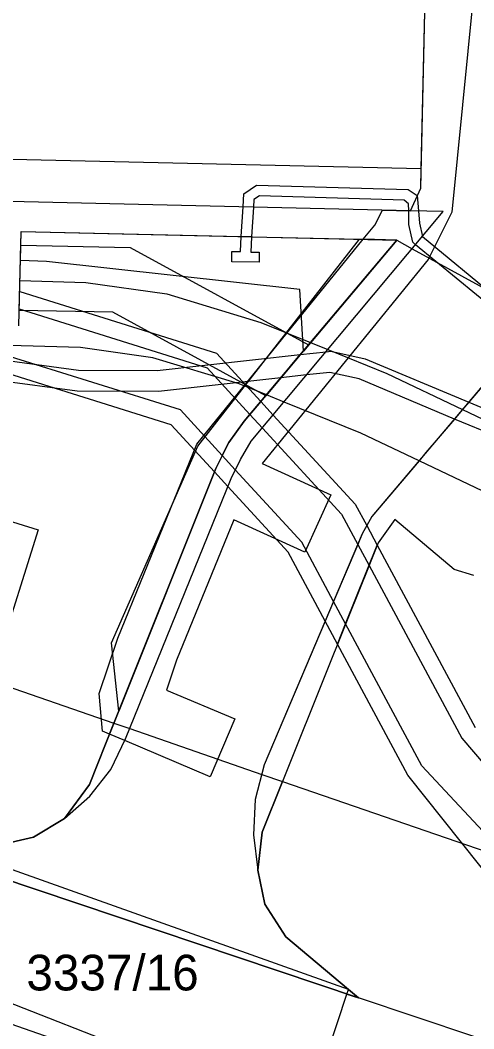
# Model space of a CAD drawing. Extents: x -593183 to -588034, y -1130415 to -1124994.
# Drawn here: x -592256.65 to -592235.02, y -1128440.03 to -1128391.95 of the extents above; entities that cross this region are included whole.
import ezdxf

# ---------------------------------------------------------------- set-up
doc = ezdxf.new("R2010")
doc.units = 0
for name, color, linetype in [('Vrstva 1', 7, 'Continuous'), ('Vrstva 18', 7, 'Continuous'), ('Vrstva 27', 7, 'Continuous')]:
    doc.layers.add(name, color=color, linetype=linetype)

msp = doc.modelspace()

# ---------------------------------------------------------------- linework, layer by layer
at = {"layer": 'Vrstva 1'}
for p, q in [((-592237.53, -1128399.02), (-592237.22, -1128385.45)), ((-592275.54, -1128398.15), (-592237.53, -1128399.02)), ((-592237.55, -1128399.95), (-592237.53, -1128399.02)), ((-592238.04, -1128401.03), (-592237.55, -1128399.95)), ((-592256.71, -1128406.52), (-592256.61, -1128402.02)), ((-592256.61, -1128402.02), (-592238.68, -1128402.43)), ((-592245.97, -1128411.07), (-592238.68, -1128402.43)), ((-592246.7, -1128412.08), (-592245.97, -1128411.07)), ((-592247.32, -1128413.32), (-592246.7, -1128412.08)), ((-592253.35, -1128428.39), (-592247.32, -1128413.32)), ((-592238.79, -1128415.75), (-592239.58, -1128416.86)), ((-592235.96, -1128418.14), (-592238.79, -1128415.75)), ((-592239.58, -1128416.86), (-592245.11, -1128430.66)), ((-592235.01, -1128418.42), (-592235.96, -1128418.14)), ((-592292.81, -1128424.89), (-592233.79, -1128447.89)), ((-592293.27, -1128427.22), (-592233.79, -1128447.89)), ((-592254.54, -1128430), (-592253.35, -1128428.39)), ((-592256.01, -1128430.9), (-592254.54, -1128430)), ((-592257.79, -1128431.31), (-592256.01, -1128430.9)), ((-592245.11, -1128430.66), (-592245.32, -1128432.47)), ((-592262.05, -1128431.32), (-592240.51, -1128438.56)), ((-592245.32, -1128432.47), (-592244.98, -1128434.09)), ((-592244.98, -1128434.09), (-592243.98, -1128435.65)), ((-592243.98, -1128435.65), (-592240.51, -1128438.56)), ((-592235.02, -1128440.4), (-592240.51, -1128438.56))]:
    msp.add_line(p, q, dxfattribs=at)
for points in [[(-592211.75, -1128388.7), (-592213.01, -1128392.48), (-592216.38, -1128400.85), (-592217.2, -1128402.32), (-592218.27, -1128403.62), (-592219.56, -1128404.7), (-592221.41, -1128405.52), (-592223.4, -1128405.89), (-592230.17, -1128405.79), (-592231.22, -1128405.97), (-592232.15, -1128406.49), (-592239.88, -1128415.6), (-592240.34, -1128416.44), (-592245.01, -1128427.45), (-592245.44, -1128429.09), (-592245.52, -1128430.78), (-592245.32, -1128432.47)], [(-592238.04, -1128401.03), (-592277.64, -1128400.11), (-592277.61, -1128398.63), (-592281.59, -1128398.55), (-592281.41, -1128392.14), (-592283.39, -1128392.47), (-592285.17, -1128393.38), (-592286.61, -1128394.54), (-592287.74, -1128396), (-592288.65, -1128397.62)], [(-592254.54, -1128430), (-592253.32, -1128428.94), (-592252.33, -1128427.66), (-592251.62, -1128426.21), (-592246.59, -1128413.8), (-592246.14, -1128412.89), (-592245.63, -1128412.02), (-592236.47, -1128401.07), (-592238.04, -1128401.03)]]:
    msp.add_lwpolyline(points, dxfattribs=at)
at = {"layer": 'Vrstva 27'}
for p, q in [((-592237.55, -1128399.95), (-592237.22, -1128385.45)), ((-592235.02, -1128390.64), (-592236.07, -1128401.1)), ((-592245.98, -1128400.22), (-592245.38, -1128399.82)), ((-592245.38, -1128399.82), (-592238.14, -1128400.02)), ((-592238.14, -1128400.02), (-592237.71, -1128400.3)), ((-592238.04, -1128401.03), (-592237.55, -1128399.95)), ((-592246.02, -1128400.84), (-592245.98, -1128400.22)), ((-592245.5, -1128400.5), (-592245.52, -1128400.86)), ((-592245.24, -1128400.32), (-592245.5, -1128400.5)), ((-592238.34, -1128400.52), (-592245.24, -1128400.32)), ((-592238.13, -1128400.7), (-592238.34, -1128400.52)), ((-592237.71, -1128400.3), (-592237.65, -1128401.04)), ((-592246.11, -1128402.26), (-592246.02, -1128400.84)), ((-592245.52, -1128400.86), (-592245.61, -1128402.27)), ((-592239.74, -1128401.72), (-592239.37, -1128401)), ((-592239.37, -1128401), (-592238.04, -1128401.03)), ((-592238.12, -1128401.03), (-592238.13, -1128400.7)), ((-592238.12, -1128401.2), (-592238.12, -1128401.03)), ((-592237.65, -1128401.04), (-592237.61, -1128401.63)), ((-592236.07, -1128401.1), (-592237.2, -1128403.35)), ((-592238.11, -1128401.69), (-592238.12, -1128401.2)), ((-592237.61, -1128401.63), (-592237.46, -1128402.26)), ((-592256.64, -1128403.4), (-592256.61, -1128402.02)), ((-592256.62, -1128402.68), (-592256.61, -1128402.02)), ((-592256.61, -1128402.02), (-592238.68, -1128402.43)), ((-592256.61, -1128402.02), (-592246.11, -1128402.26)), ((-592240.29, -1128402.39), (-592239.74, -1128401.72)), ((-592237.93, -1128402.53), (-592238.11, -1128401.69)), ((-592248.22, -1128412.16), (-592240.29, -1128402.39)), ((-592248.18, -1128412.26), (-592240.46, -1128402.39)), ((-592246.15, -1128402.98), (-592246.11, -1128402.26)), ((-592245.61, -1128402.27), (-592246.11, -1128402.26)), ((-592246.11, -1128402.26), (-592245.61, -1128402.27)), ((-592246.11, -1128402.26), (-592245.61, -1128402.27)), ((-592238.68, -1128402.43), (-592245.97, -1128411.07)), ((-592245.97, -1128411.07), (-592238.68, -1128402.43)), ((-592238.68, -1128402.43), (-592245.97, -1128411.07)), ((-592245.97, -1128411.07), (-592238.68, -1128402.43)), ((-592245.61, -1128402.27), (-592245.65, -1128403)), ((-592245.61, -1128402.27), (-592240.46, -1128402.39)), ((-592238.68, -1128402.43), (-592243.14, -1128407.72)), ((-592238.68, -1128402.43), (-592242.8, -1128407.32)), ((-592240.46, -1128402.39), (-592238.68, -1128402.43)), ((-592240.46, -1128402.39), (-592240.29, -1128402.39)), ((-592240.29, -1128402.39), (-592238.68, -1128402.43)), ((-592240.29, -1128402.39), (-592238.68, -1128402.43)), ((-592238.68, -1128402.43), (-592240.29, -1128402.39)), ((-592238.68, -1128402.43), (-592237.95, -1128402.84)), ((-592237.79, -1128402.65), (-592237.93, -1128402.53)), ((-592237.46, -1128402.26), (-592232.23, -1128406.59)), ((-592256.69, -1128405.78), (-592256.62, -1128402.68)), ((-592256.64, -1128403.18), (-592256.62, -1128402.68)), ((-592256.62, -1128402.68), (-592251.41, -1128402.78)), ((-592251.41, -1128402.78), (-592242.9, -1128407.43)), ((-592246.56, -1128403.47), (-592246.55, -1128402.98)), ((-592246.55, -1128402.98), (-592246.15, -1128402.98)), ((-592245.65, -1128403), (-592245.25, -1128403)), ((-592245.25, -1128403), (-592245.26, -1128403.49)), ((-592237.95, -1128402.84), (-592231.74, -1128406.26)), ((-592232.56, -1128406.97), (-592237.79, -1128402.65)), ((-592256.64, -1128403.4), (-592256.64, -1128403.18)), ((-592255.4, -1128403.45), (-592256.64, -1128403.4)), ((-592255.4, -1128403.45), (-592256.64, -1128403.4)), ((-592243.32, -1128404.79), (-592255.4, -1128403.45)), ((-592243.32, -1128404.79), (-592255.4, -1128403.45)), ((-592245.26, -1128403.49), (-592246.56, -1128403.47)), ((-592237.2, -1128403.35), (-592245.11, -1128413.08)), ((-592256.66, -1128404.36), (-592253.52, -1128404.45)), ((-592253.52, -1128404.45), (-592249.65, -1128405)), ((-592256.67, -1128404.88), (-592247.29, -1128407.82)), ((-592249.65, -1128405), (-592245.17, -1128406.36)), ((-592243.14, -1128407.72), (-592243.32, -1128404.79)), ((-592243.14, -1128407.72), (-592243.32, -1128404.79)), ((-592256.69, -1128405.7), (-592247.73, -1128408.52)), ((-592256.69, -1128405.7), (-592247.73, -1128408.52)), ((-592252.23, -1128405.86), (-592256.69, -1128405.78)), ((-592244.94, -1128409.85), (-592252.23, -1128405.86)), ((-592245.17, -1128406.36), (-592242.8, -1128407.32)), ((-592253.78, -1128407.55), (-592265.26, -1128407.21)), ((-592242.8, -1128407.32), (-592244.91, -1128409.81)), ((-592244.91, -1128409.81), (-592242.8, -1128407.32)), ((-592242.8, -1128407.32), (-592242.9, -1128407.43)), ((-592242.8, -1128407.32), (-592241.98, -1128407.65)), ((-592232.56, -1128406.97), (-592235.26, -1128410.15)), ((-592261.52, -1128407.61), (-592253.87, -1128408.63)), ((-592250.32, -1128408.04), (-592253.78, -1128407.55)), ((-592250.12, -1128408.65), (-592243.29, -1128407.89)), ((-592247.29, -1128407.82), (-592245.17, -1128410.12)), ((-592242.9, -1128407.43), (-592244.94, -1128409.85)), ((-592243.29, -1128407.89), (-592244.22, -1128409)), ((-592244.22, -1128409), (-592243.29, -1128407.89)), ((-592243.29, -1128407.89), (-592242.06, -1128407.76)), ((-592242.9, -1128407.43), (-592243.14, -1128407.72)), ((-592242.06, -1128407.76), (-592241.83, -1128407.73)), ((-592241.98, -1128407.65), (-592239.16, -1128408.79)), ((-592241.83, -1128407.73), (-592240.19, -1128408.09)), ((-592249.01, -1128410.53), (-592257.36, -1128407.91)), ((-592246.21, -1128409.28), (-592250.32, -1128408.04)), ((-592240.19, -1128408.09), (-592235.26, -1128410.15)), ((-592253.93, -1128409.63), (-592261.6, -1128408.61)), ((-592249.45, -1128411.23), (-592257.49, -1128408.71)), ((-592249.45, -1128411.23), (-592257.49, -1128408.71)), ((-592253.87, -1128408.63), (-592250.12, -1128408.65)), ((-592247.73, -1128408.52), (-592245.69, -1128410.74)), ((-592247.73, -1128408.52), (-592245.69, -1128410.74)), ((-592242.99, -1128408.86), (-592244.22, -1128409)), ((-592241.89, -1128408.74), (-592242.99, -1128408.86)), ((-592240.49, -1128409.05), (-592241.89, -1128408.74)), ((-592239.16, -1128408.79), (-592235.56, -1128410.51)), ((-592244.22, -1128409), (-592250.06, -1128409.65)), ((-592244.91, -1128409.81), (-592246.21, -1128409.28)), ((-592235.94, -1128410.96), (-592240.49, -1128409.05)), ((-592250.06, -1128409.65), (-592253.93, -1128409.63)), ((-592244.06, -1128410.15), (-592244.91, -1128409.81)), ((-592245.17, -1128410.12), (-592245.97, -1128411.07)), ((-592245.97, -1128411.07), (-592245.17, -1128410.12)), ((-592245.17, -1128410.12), (-592244.58, -1128410.77)), ((-592240.4, -1128411.63), (-592244.06, -1128410.15)), ((-592235.26, -1128410.15), (-592235.56, -1128410.51)), ((-592235.26, -1128410.15), (-592232.71, -1128411.22)), ((-592247.01, -1128412.7), (-592249.01, -1128410.53)), ((-592245.69, -1128410.74), (-592245.97, -1128411.07)), ((-592245.69, -1128410.74), (-592245.97, -1128411.07)), ((-592245.97, -1128411.07), (-592245.69, -1128410.74)), ((-592245.69, -1128410.74), (-592245.1, -1128411.39)), ((-592244.58, -1128410.77), (-592240.67, -1128415.02)), ((-592235.56, -1128410.51), (-592235.89, -1128410.9)), ((-592235.56, -1128410.51), (-592230.04, -1128413.13)), ((-592247.38, -1128413.48), (-592249.45, -1128411.23)), ((-592247.38, -1128413.48), (-592249.45, -1128411.23)), ((-592245.97, -1128411.07), (-592246.7, -1128412.08)), ((-592246.7, -1128412.08), (-592245.97, -1128411.07)), ((-592245.97, -1128411.07), (-592246.7, -1128412.08)), ((-592245.97, -1128411.07), (-592246.7, -1128412.08)), ((-592245.97, -1128411.07), (-592246.7, -1128412.08)), ((-592245.97, -1128411.07), (-592246.7, -1128412.08)), ((-592246.7, -1128412.08), (-592245.97, -1128411.07)), ((-592246.7, -1128412.08), (-592245.97, -1128411.07)), ((-592246.7, -1128412.08), (-592245.97, -1128411.07)), ((-592235.94, -1128410.96), (-592237.3, -1128412.55)), ((-592235.89, -1128410.9), (-592235.94, -1128410.96)), ((-592233.11, -1128412.14), (-592235.94, -1128410.96)), ((-592245.1, -1128411.39), (-592241.33, -1128415.49)), ((-592237.63, -1128412.95), (-592240.4, -1128411.63)), ((-592252, -1128421.4), (-592248.22, -1128412.16)), ((-592246.7, -1128412.08), (-592247.32, -1128413.32)), ((-592247.32, -1128413.32), (-592246.7, -1128412.08)), ((-592246.7, -1128412.08), (-592247.32, -1128413.32)), ((-592247.32, -1128413.32), (-592246.7, -1128412.08)), ((-592247.32, -1128413.32), (-592246.7, -1128412.08)), ((-592246.7, -1128412.08), (-592247.01, -1128412.7)), ((-592246.7, -1128412.08), (-592247.01, -1128412.7)), ((-592246.7, -1128412.08), (-592247.01, -1128412.7)), ((-592247.01, -1128412.7), (-592246.7, -1128412.08)), ((-592252.3, -1128421.63), (-592248.18, -1128412.26)), ((-592247.01, -1128412.7), (-592247.32, -1128413.32)), ((-592247.01, -1128412.7), (-592247.32, -1128413.32)), ((-592246.39, -1128413.39), (-592247.01, -1128412.7)), ((-592237.3, -1128412.55), (-592237.63, -1128412.95)), ((-592265.44, -1128413.19), (-592255.79, -1128416.25)), ((-592245.11, -1128413.08), (-592241.84, -1128414.57)), ((-592237.63, -1128412.95), (-592239.88, -1128415.6)), ((-592232.11, -1128415.58), (-592237.63, -1128412.95)), ((-592253.35, -1128428.39), (-592247.32, -1128413.32)), ((-592247.32, -1128413.32), (-592252.39, -1128425.99)), ((-592252.39, -1128425.99), (-592247.32, -1128413.32)), ((-592247.32, -1128413.32), (-592251.95, -1128424.89)), ((-592247.32, -1128413.32), (-592247.38, -1128413.48)), ((-592247.32, -1128413.32), (-592247.38, -1128413.48)), ((-592247.38, -1128413.48), (-592247.32, -1128413.32)), ((-592246.74, -1128414.18), (-592247.38, -1128413.48)), ((-592243.22, -1128416.83), (-592246.39, -1128413.39)), ((-592243.87, -1128417.3), (-592246.74, -1128414.18)), ((-592241.84, -1128414.57), (-592243.08, -1128417.3)), ((-592240.67, -1128415.02), (-592240.12, -1128416.04)), ((-592241.33, -1128415.49), (-592240.55, -1128416.94)), ((-592239.88, -1128415.6), (-592240.12, -1128416.04)), ((-592246.46, -1128415.76), (-592249.19, -1128422.45)), ((-592243.08, -1128417.3), (-592246.46, -1128415.76)), ((-592240.12, -1128416.04), (-592240.34, -1128416.44)), ((-592240.12, -1128416.04), (-592239.62, -1128416.97)), ((-592255.79, -1128416.25), (-592258.56, -1128424.96)), ((-592240.34, -1128416.44), (-592240.55, -1128416.94)), ((-592241.7, -1128419.66), (-592243.22, -1128416.83)), ((-592240.55, -1128416.94), (-592241.7, -1128419.66)), ((-592241.13, -1128420.73), (-592239.62, -1128416.97)), ((-592239.62, -1128416.97), (-592241.13, -1128420.73)), ((-592240.55, -1128416.94), (-592240.01, -1128417.94)), ((-592239.62, -1128416.97), (-592234.95, -1128425.67)), ((-592242.1, -1128420.6), (-592243.87, -1128417.3)), ((-592240.01, -1128417.94), (-592241.52, -1128421.69)), ((-592241.13, -1128420.73), (-592240.01, -1128417.94)), ((-592240.01, -1128417.94), (-592235.59, -1128426.17)), ((-592241.7, -1128419.66), (-592242.1, -1128420.6)), ((-592241.13, -1128420.73), (-592241.7, -1128419.66)), ((-592242.1, -1128420.6), (-592245.01, -1128427.45)), ((-592241.52, -1128421.69), (-592242.1, -1128420.6)), ((-592241.52, -1128421.69), (-592241.13, -1128420.73)), ((-592237.5, -1128427.49), (-592241.13, -1128420.73)), ((-592252.88, -1128424.04), (-592252, -1128421.4)), ((-592251.95, -1128424.89), (-592252.3, -1128421.63)), ((-592238.17, -1128427.93), (-592241.52, -1128421.69)), ((-592249.19, -1128422.45), (-592249.67, -1128423.88)), ((-592259.33, -1128422.99), (-592252.18, -1128425.46)), ((-592252.73, -1128425.84), (-592252.88, -1128424.04)), ((-592249.67, -1128423.88), (-592246.42, -1128425.26)), ((-592252.18, -1128425.46), (-592253.35, -1128428.39)), ((-592253.35, -1128428.39), (-592252.18, -1128425.46)), ((-592252.18, -1128425.46), (-592251.42, -1128425.72)), ((-592246.42, -1128425.26), (-592247.59, -1128428.02)), ((-592252.39, -1128425.99), (-592252.73, -1128425.84)), ((-592251.66, -1128426.29), (-592252.39, -1128425.99)), ((-592251.42, -1128425.72), (-592245.13, -1128427.9)), ((-592235.59, -1128426.17), (-592228.21, -1128434.89)), ((-592247.59, -1128428.02), (-592251.66, -1128426.29)), ((-592245.01, -1128427.45), (-592245.44, -1128429.09)), ((-592228.66, -1128436.97), (-592237.5, -1128427.49)), ((-592245.13, -1128427.9), (-592244.14, -1128428.24)), ((-592228.82, -1128439.66), (-592238.17, -1128427.93)), ((-592253.35, -1128428.39), (-592254.54, -1128430)), ((-592254.54, -1128430), (-592253.35, -1128428.39)), ((-592254.54, -1128430), (-592253.35, -1128428.39)), ((-592245.11, -1128430.66), (-592244.14, -1128428.24)), ((-592244.14, -1128428.24), (-592245.11, -1128430.66)), ((-592244.14, -1128428.24), (-592234.4, -1128431.6)), ((-592245.44, -1128429.09), (-592245.52, -1128430.78)), ((-592254.54, -1128430), (-592256.01, -1128430.9)), ((-592256.01, -1128430.9), (-592254.54, -1128430)), ((-592256.01, -1128430.9), (-592254.54, -1128430)), ((-592256.01, -1128430.9), (-592257.79, -1128431.31)), ((-592257.79, -1128431.31), (-592256.01, -1128430.9)), ((-592257.79, -1128431.31), (-592256.01, -1128430.9)), ((-592245.52, -1128430.78), (-592245.32, -1128432.47)), ((-592245.32, -1128432.47), (-592245.11, -1128430.66)), ((-592245.11, -1128430.66), (-592245.32, -1128432.47)), ((-592240.51, -1128438.56), (-592262.05, -1128431.32)), ((-592241, -1128438.15), (-592260.2, -1128431.32)), ((-592244.98, -1128434.09), (-592245.32, -1128432.47)), ((-592245.32, -1128432.47), (-592244.98, -1128434.09)), ((-592245.32, -1128432.47), (-592244.98, -1128434.09)), ((-592243.98, -1128435.65), (-592244.98, -1128434.09)), ((-592244.98, -1128434.09), (-592243.98, -1128435.65)), ((-592244.98, -1128434.09), (-592243.98, -1128435.65)), ((-592241, -1128438.15), (-592243.98, -1128435.65)), ((-592243.98, -1128435.65), (-592240.51, -1128438.56)), ((-592243.98, -1128435.65), (-592241, -1128438.15)), ((-592241.07, -1128438.37), (-592241, -1128438.15)), ((-592240.51, -1128438.56), (-592241, -1128438.15)), ((-592241, -1128438.15), (-592240.51, -1128438.56)), ((-592243.02, -1128444.29), (-592241.07, -1128438.37)), ((-592241.07, -1128438.37), (-592240.51, -1128438.56)), ((-592240.51, -1128438.56), (-592241.07, -1128438.37))]:
    msp.add_line(p, q, dxfattribs=at)

# ---------------------------------------------------------------- texts
at = {"layer": 'Vrstva 18'}
msp.add_text('3337/16', height=1.7, dxfattribs=at).set_placement((-592256.354, -1128438.2))

doc.saveas('drawing.dxf')
